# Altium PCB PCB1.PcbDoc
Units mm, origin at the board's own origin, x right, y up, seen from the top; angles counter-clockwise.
Board outline 114.17 x 52.7 mm, 2 copper layers (Top Layer, Bottom Layer); 27 components, 26 nets, 108 pads, 2 vias.
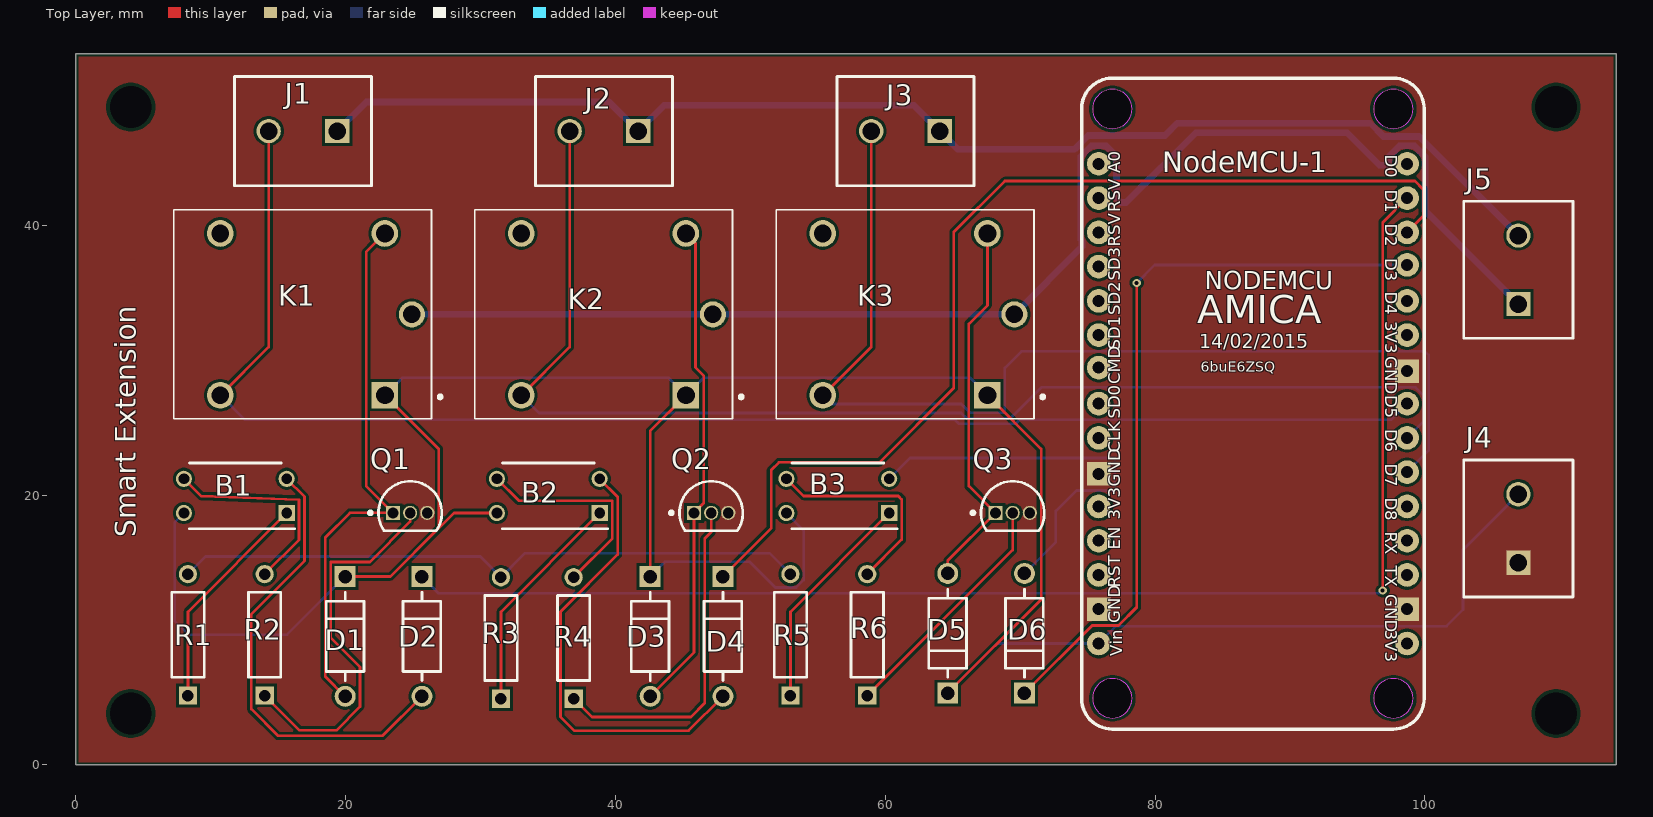
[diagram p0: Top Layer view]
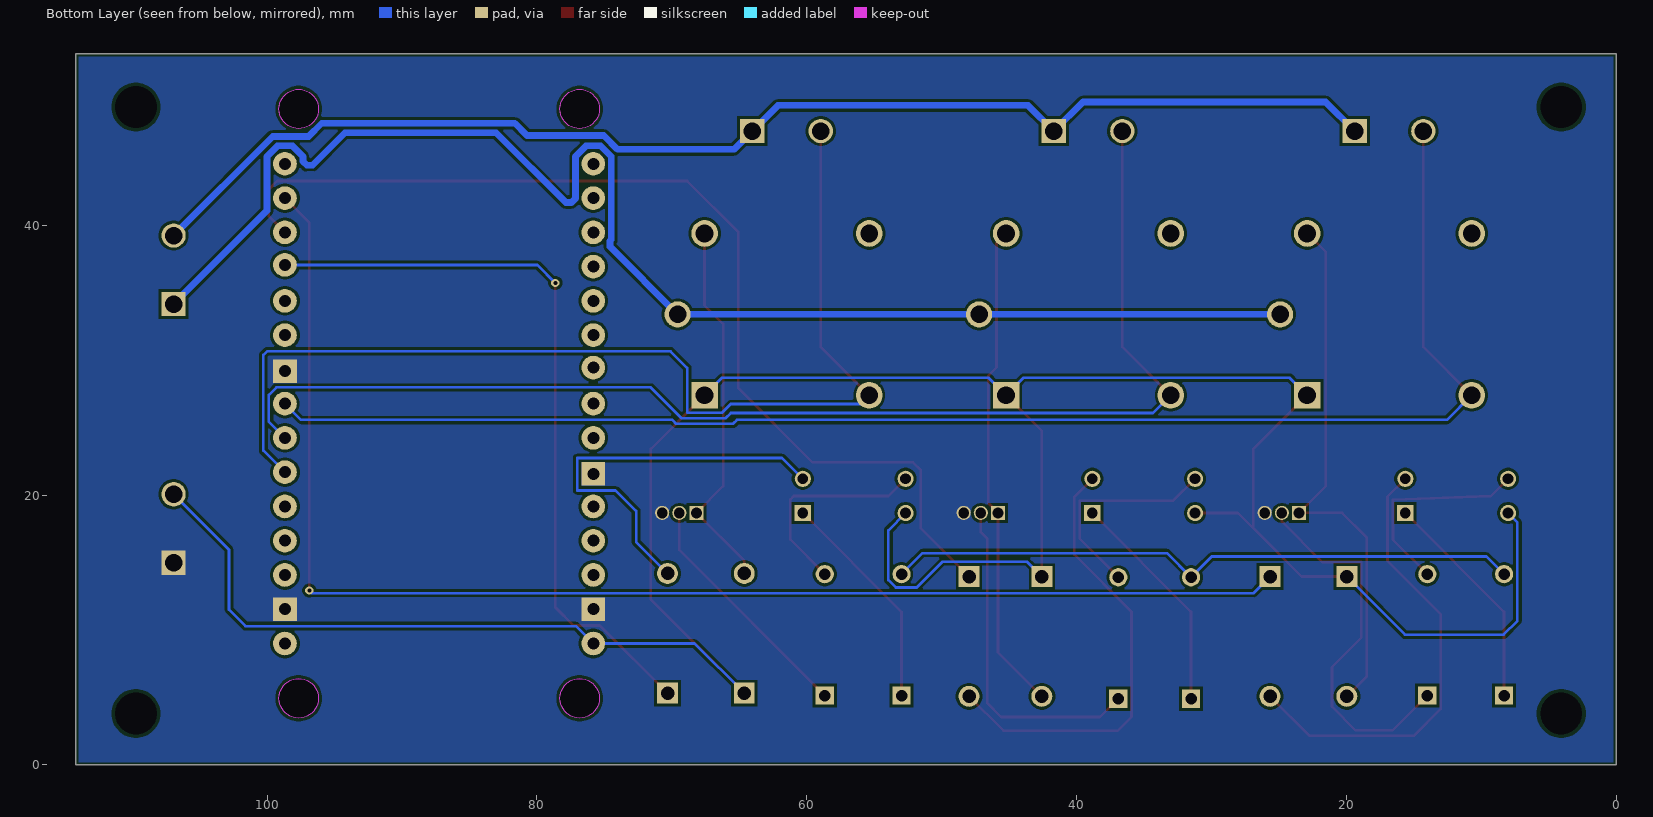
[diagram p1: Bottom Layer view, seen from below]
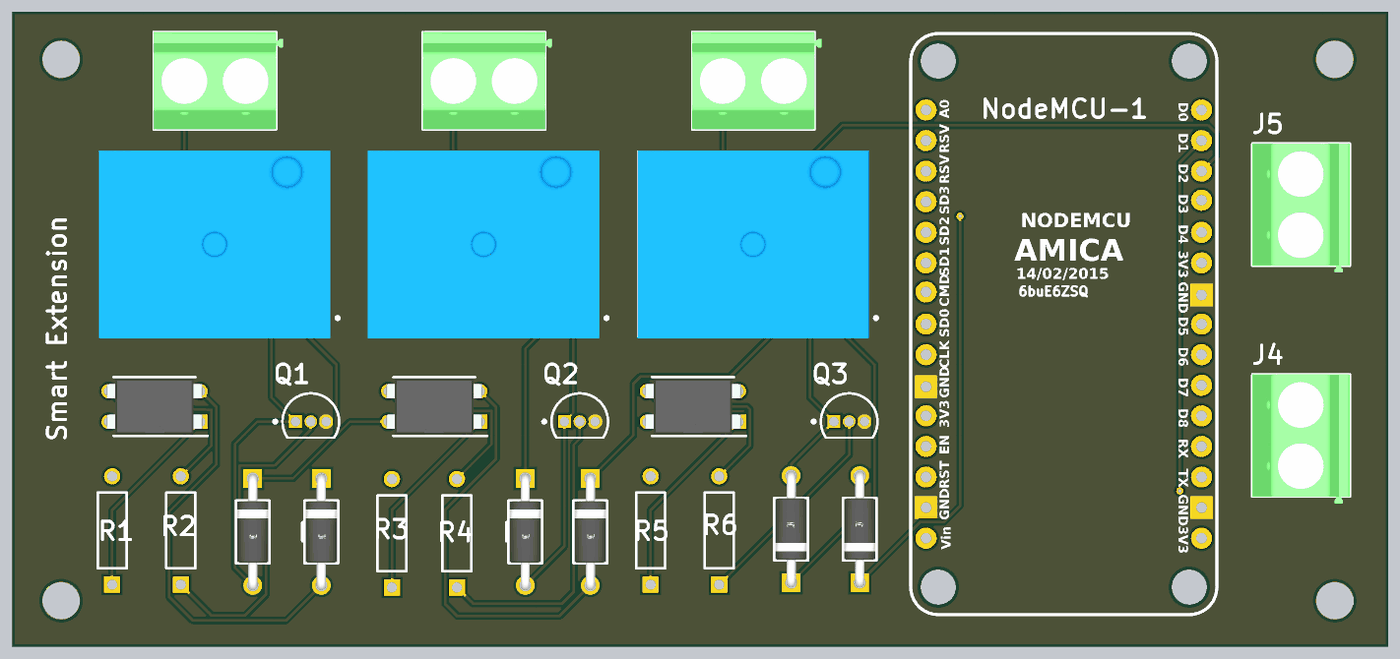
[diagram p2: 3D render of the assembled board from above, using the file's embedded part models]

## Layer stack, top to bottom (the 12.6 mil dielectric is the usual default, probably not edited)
Top Solder: solder mask 0.0102, Solder Resist, Dk 3.5
Top Layer: signal copper 0.0356
Dielectric 1: dielectric 0.32, FR-4, Dk 4.8
Bottom Layer: signal copper 0.0356
Bottom Solder: solder mask 0.0102, Solder Resist, Dk 3.5

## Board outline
0,0 114.173,0 114.173,52.705 0,52.705

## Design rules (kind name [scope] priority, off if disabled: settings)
BoardOutlineClearance [All] p1: gap=0.2 ignorepadtopadclearanceinfootprint=FALSE
Clearance [All] p1: gap=0.203 ignorepadtopadclearanceinfootprint=FALSE except(0.25: Arc-Hole Track-Hole SMDPad-Hole THPad-Hole Via-Hole Fill-Hole Poly-Hole Region-Hole Text-Hole)
ComponentClearance [All] p1: gap=0.127 collisioncheckmode=3 verticalgap=0.127 showdistances=TRUE
DiffPairsRouting [All] p1: maxlimit=0.381 minlimit=0.203 mostfreqgap=0.203 toplayer_minwidth=0.203 toplayer_maxwidth=25.4 toplayer_prefwidth=0.203 bottomlayer_minwidth=0.203 bottomlayer_maxwidth=25.4 bottomlayer_prefwidth=0.203 maxuncoupledlength=12.7
Height [All] p1: minheight=0 maxheight=1816.048 prefheight=12.7
HoleSize [All] p1: absolutevalues=TRUE maxlimit=6.3 minlimit=0.3 maxpercent=80.000 minpercent=20.000
HoleToHoleClearance [All] p1: gap=0.25 allowstackedmicrovias=FALSE
MinimumAnnularRing [All] p1: minimumring=0.076
MinimumSolderMaskSliver [All] p1: minsoldermaskwidth=0
PlaneClearance [All] p1: clearance=0.203
PlaneConnect PlaneConnectPowerPads [InPadClass('PowerPads')] p1: planeconnectstyle=Direct reliefexpansion=0.508 reliefentries=4 reliefconductorwidth=0.254 reliefairgap=0.254
PlaneConnect [All] p2: pad.planeconnectstyle=Relief pad.reliefexpansion=0.3 pad.reliefentries=4 pad.reliefconductorwidth=0.203 pad.reliefairgap=0.203 via.planeconnectstyle=Direct via.reliefexpansion=0.3 via.reliefentries=4 via.reliefconductorwidth=0.127 via.reliefairgap=0.127
PolygonConnect PolygonConnectPowerPads [All vs (InPadClass('PowerPads'))] p1: connectstyle=Direct reliefconductorwidth=0.254 reliefentries=4 polygonreliefangle="90 Angle" airgapwidth=0.254
PolygonConnect [All] p2: connectstyle=Direct reliefconductorwidth=0.203 reliefentries=4 polygonreliefangle="90 Angle" airgapwidth=0.203
RoutingVias [All] p1: holewidth=0.3 width=0.6 viastyle="Through Hole" minholewidth=0.3 minwidth=0.6 maxholewidth=0.6 maxwidth=6.6
SilkToSilkClearance [All] p1: silktosilkclearance=0
SilkToSolderMaskClearance [IsPad] p1: minsilkscreentomaskgap=0.127 clearancetoexposedcopper=TRUE
SolderMaskExpansion [All] p1: expansion=0.075 istentingtop=FALSE
Width [All] p1: maxlimit=25.4 minlimit=0.203 preferedwidth=0.203 minimp=50.000000 maximp=50.000000 favimp=50.000000
20 further rules are at their usual default settings.

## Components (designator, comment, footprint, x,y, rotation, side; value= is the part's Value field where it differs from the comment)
B1 "PC817X2NSZ0F" DIP762W60P254L458H400Q4N 11.811,19.939 r180 top
B2 "PC817X2NSZ0F" DIP762W60P254L458H400Q4N 35.015,19.939 r180 top
B3 "PC817X2NSZ0F" DIP762W60P254L458H400Q4N 56.478,19.939 r180 top
D1 "1N4007" FP-1N4007-MFG 19.959,9.525 r270 top value=15pF
D2 "1N4007" FP-1N4007-MFG 25.651,9.525 r270 top value=15pF
D3 "1N4007" FP-1N4007-MFG 42.571,9.525 r270 top value=15pF
D4 "1N4007" FP-1N4007-MFG 47.966,9.525 r270 top value=15pF
D5 "1N4007" FP-1N4007-MFG 64.626,9.755 r90 top value=15pF
D6 "1N4007" FP-1N4007-MFG 70.318,9.755 r90 top value=15pF
J1 "1729128" PHOE-1729128-2_V 16.829,46.99 r180 top
J2 "1729128" PHOE-1729128-2_V 39.144,46.99 r180 top
J3 "1729128" PHOE-1729128-2_V 61.496,46.99 r180 top
J4 "1729128" PHOE-1729128-2_V 106.934,17.526 r90 top
J5 "1729128" PHOE-1729128-2_V 106.934,36.703 r90 top
K1 "SRD-05VDC-SL-C" RELAY_SRD-05VDC-SL-C 16.801,33.401 r180 top
K2 "SRD-05VDC-SL-C" RELAY_SRD-05VDC-SL-C 39.116,33.401 r180 top
K3 "SRD-05VDC-SL-C" RELAY_SRD-05VDC-SL-C 61.468,33.401 r180 top
NodeMCU-1 "NodeMCU V1.0 ESP-12E" "NodeMCU V1.0 ESP-12E" 74.524,50.809 r0 top
Q1 "BC547B" ONSC-TO-92-3-29-11 24.776,18.684 r0 top
Q2 "BC547B" ONSC-TO-92-3-29-11 47.091,18.684 r0 top
Q3 "BC547B" ONSC-TO-92-3-29-11 69.443,18.684 r0 top
R1 "1K" RESA60-630X240 8.301,9.64 r90 top
R2 "1K" RESA60-630X240 13.993,9.64 r90 top
R3 "1K" RESA60-630X240 31.505,9.41 r90 top
R4 "1K" RESA60-630X240 36.9,9.41 r90 top
R5 "1K" RESA60-630X240 52.968,9.64 r90 top
R6 "1K" RESA60-630X240 58.66,9.64 r90 top

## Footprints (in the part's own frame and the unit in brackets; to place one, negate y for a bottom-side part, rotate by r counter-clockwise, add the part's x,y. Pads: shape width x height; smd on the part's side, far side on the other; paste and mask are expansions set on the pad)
DIP762W60P254L458H400Q4N [mm]
  rect 1.2x1.2 hole 0.8: 1(-3.81,1.27)
  round 1.2 hole 0.8: 2(-3.81,-1.27) 3(3.81,-1.27) 4(3.81,1.27)
  silkscreen extent -4.41,-2.44 3.4,2.44, body extent -3.96,-2.29 3.96,2.29, height 4
FP-1N4007-MFG [mm]
  rect 1.55x1.55 hole 1 paste-1000 mask+0: 1(-4.44,0)
  round 1.55 hole 1 paste-1000 mask+0: 2(4.44,0)
  silkscreen extent -3.27,-1.4 3.27,1.4, body extent -5.32,-1.5 5.32,1.5, height 0.25
"NodeMCU V1.0 ESP-12E" [mil]
  round 115 hole 115 unplated paste-300 mask-300: 0(91,-1806) 0(91,-86) 0(911,-1806) 0(911,-86)
  round 69 hole 35: 3V3(51,-1246) 3V3(951,-1646) 3V3(951,-746) A0(51,-246) CLK(51,-1046) CMD(51,-841) D0(951,-246) D1(951,-346) D2(951,-446) D3(951,-541) D4(951,-646) D5(951,-946) D6(951,-1046) D7(951,-1146) D8(951,-1246) EN(51,-1346) RST(51,-1446) RSV(51,-446) RSV(51,-346) RX(951,-1346) SD0(51,-946) SD1(51,-746) SD2(51,-646) SD3(51,-546) TX(951,-1446) VIN(51,-1646)
  rect 69x69 hole 35: GND(51,-1546) GND(51,-1151) GND(951,-1546) GND(951,-851)
  Keep-Out Layer circle w2: c911,-1806 r57.5
  Keep-Out Layer circle w2: c91,-1806 r57.5
  Keep-Out Layer circle w2: c911,-86 r57.5
  Keep-Out Layer circle w2: c91,-86 r57.5
  silkscreen extent 1,-1896 1001,4
ONSC-TO-92-3-29-11 [mm] "TO, 3-Leads, Body Dia 4.7mm, Pitch 1.27mm"
  rect 1.05x1.05 hole 0.8: 1(-1.27,0)
  round 1.05 hole 0.8: 2(0,0) 3(1.27,0)
  silkscreen extent -3.07,-1.34 2.35,2.35, body extent -2.35,-1.33 2.36,2.36, height 7.87
PHOE-1729128-2_V [mm] "Receptacle, 2-Leads, Body 8.1x10.16mm, Pitch 5.08mm"
  rect 1.8x1.8 hole 1.3: 1(-2.54,0)
  round 1.8 hole 1.3: 2(2.54,0)
  silkscreen extent -5.08,-4.05 5.08,4.05, body extent -5.65,-4.05 5.08,4.05, height 10.01
RELAY_SRD-05VDC-SL-C [mm]
  rect 1.98x1.98 / inner round 1.98 / far side rect 1.98x1.98 hole 1.32: A1(-6.1,6)
  round 1.98 hole 1.32: A2(-6.1,-6) NC(6.1,6) NO(6.1,-6)
  round 1.935 hole 1.29: COM(-8.1,0)
  silkscreen extent -10.3,-7.75 9.55,7.75, body extent -9.6,-7.8 9.6,7.8, height 15.8
RESA60-630X240 [mm] "Axial Resistor, 2-Leads, Dia 2.4mm, Body Length 6.3mm"
  rect 1.35x1.35 hole 0.85: 1(-4.5,0)
  round 1.35 hole 0.85: 2(4.5,0)
  silkscreen extent -3.15,-1.2 3.15,1.2, body extent -3.15,-1.2 3.15,1.2, height 2.4

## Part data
B1 B2 B3: "Photocoupler 1-CH Transistor 4-Pin PDIP Sharp PC817X2NSZ0F DC Input Transistor Output Optocoupler, Through Hole, 4-Pin PDIP", Manufacturer_Name="Sharp Microelectronics", Mouser Part Number=N/A
D1 D2 D3 D4 D5 D6: library part CMP-123542-000001-1, "Rectifier diode 1000 V 1 A DO-41, ,", Capacitance=15pF, Forward Current=1A, Manufacturer=Diotec, Max Junction Temp=+175°C, Max Repetitive Reverse Voltage=1000V, Max Surge Forward Current=27A, Peak Reverse Current=5uA, Temperature="-50°C to +175°C", Temperature Range Low=-50°C
J1 J2 J3 J4 J5: library part CMP-2000-05815-1, "PCB Terminal Block, 13.5 A, 400 V, 2-Pin THD, RoHS, Bulk", Current Rating=13500mA, Manufacturer="Phoenix Contact", Package Description="2-Pin Through Hole Device, Body 8.1 x 10.16 mm, Pitch 5.08 mm", Package Reference=1729128-2, Package Version=03/2015, Voltage Rating=400V
K1 K2 K3: "5V Trigger Relay Module For Arduino And Raspberry Pi 5V Trigger Relay Module For Arduino And Raspberry Pi", Package="NON STANDARD-5 Songle Relay"
NodeMCU-1: "NodeMCU V1.0 ESP8266 (ESP-12E)"
Q1 Q2 Q3: library part CMP-1048-01467-1, "Amplifier Transistor, NPN Silicon, 3-Pin TO-92, Bulk Box", Manufacturer="On Semiconductor"
R1 R2 R3 R4 R5 R6: library part CMP-1659-00075-1, "Axial Resistor, 1 KOhm, +/- 1%, 250 mW, -55 to 155 degC, 2-Pin THD, RoHS, Bulk", Case\Package=Axial, Max Operating Temperature="155 degC", Min Operating Temperature="-55 degC", Package Quantity=200, Power Rating="250 mW", Resistance="10 kohm", Tolerance=1%, Voltage Rating="250 V"

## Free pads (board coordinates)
  round 1.524 hole 3.1: 1(4.064,48.768) 1(109.728,3.81) 1(109.728,48.768) 4(4.064,3.81)

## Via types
v1: diameter 0.6, hole 0.3, Top Layer to Bottom Layer, 2 vias

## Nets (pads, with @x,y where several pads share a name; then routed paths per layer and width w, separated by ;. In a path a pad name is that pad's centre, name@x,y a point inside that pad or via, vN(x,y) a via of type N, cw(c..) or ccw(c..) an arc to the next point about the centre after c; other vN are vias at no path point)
+5: B1.4 B2.4 B3.4 D1.1 D3.1 D5.1 J4.2 K1.A1 K2.A1 K3.A1 NodeMCU-1.VIN | length 210.2
  Top Layer w0.203: D1.1 23.312,13.965 ; K1.A1 26.899,23.403 26.899,17.551 23.312,13.965 ; B2.4 28.021,18.669 23.317,13.965 23.312,13.965 ; D3.1 42.571,24.756 K2.A1 ; D5.1 71.552,12.24 71.552,23.417 K3.A1
  Bottom Layer w0.203: B1.4 7.315,17.983 7.315,10.668 8.331,9.652 15.646,9.652 D1.1 ; K1.A1 24.202,28.702 43.915,28.702 K2.A1 46.517,28.702 66.267,28.702 K3.A1 ; D3.1 43.668,15.062 49.936,15.062 51.841,13.157 53.391,13.157 53.95,13.716 53.95,17.387 B3.4 ; D5.1 68.312,9.001 NodeMCU-1.VIN 77.105,10.287 101.6,10.287 102.819,11.506 102.819,15.951 J4.2
+5V: R1.2 R3.2 R5.2 | length 47.2
  Bottom Layer w0.203: R1.2 9.604,15.443 29.972,15.443 R3.2 33.292,15.697 51.411,15.697 R5.2
GND: J4.1 NodeMCU-1.GND Q1.3 Q2.3 Q3.3
N: J1.1 J2.1 J3.1 J5.2 | length 95.7
  Bottom Layer w0.5: J1.1 21.528,49.149 39.525,49.149 J2.1 43.589,48.895 62.131,48.895 65.393,45.633 74.016,45.633 75.048,46.664 80.736,46.664 81.638,47.566 95.949,47.566 96.922,46.594 99.583,46.594 J5.2
NetB1_1: B1.1 R1.1 | length 16.6
  Top Layer w0.203: R1.1 8.301,11.349 B1.1
NetB1_2: B1.2 D2.2 | length 33.9
  Top Layer w0.203: B1.2 16.942,19.888 16.942,15.113 13.005,11.176 13.005,4.14 14.986,2.159 22.725,2.159 D2.2
NetB1_3: B1.3 R2.2 | length 15.6
  Top Layer w0.203: B1.3 9.271,19.939 16.535,19.66 16.535,16.683 R2.2
NetB2_1: B2.1 R3.1 | length 16.8
  Top Layer w0.203: R3.1 31.505,11.349 B2.1
NetB2_2: B2.2 D4.2 | length 33.5
  Top Layer w0.203: B2.2 40.157,19.877 40.157,15.596 35.916,11.354 35.916,3.556 36.932,2.54 45.421,2.54 D4.2
NetB2_3: B2.3 R4.2 | length 16.1
  Top Layer w0.203: B2.3 32.831,19.583 39.751,19.583 39.751,16.761 R4.2
NetB3_1: B3.1 R5.1 | length 16.6
  Top Layer w0.203: R5.1 52.968,11.349 B3.1
NetB3_2: B3.2 D6.2 | length 30.4
  Bottom Layer w0.203: B3.2 61.837,22.758 77.013,22.758 77.013,20.345 74.168,20.345 72.644,18.821 72.644,16.521 D6.2
NetB3_3: B3.3 R6.2 | length 15.8
  Top Layer w0.203: B3.3 53.938,19.939 60.96,19.939 61.214,19.685 61.214,16.694 R6.2
NetD1_2: D1.2 K1.A2 Q1.1 | length 40.3
  Top Layer w0.203: D1.2 18.473,6.571 18.473,16.837 20.32,18.684 Q1.1 21.514,20.676 21.514,38.014 K1.A2
NetD3_2: D3.2 K2.A2 Q2.1 | length 36.5
  Top Layer w0.203: D3.2 45.821,8.335 Q2.1 46.533,19.396 46.533,28.854 45.923,29.464 45.923,38.694 K2.A2
NetD5_2: D5.2 K3.A2 Q3.1 | length 28.1
  Top Layer w0.203: D5.2 64.626,15.137 Q3.1 66.192,20.665 66.192,32.69 67.568,34.065 K3.A2
NetQ1_2: Q1.2 R2.1 | length 28.3
  Top Layer w0.203: R2.1 16.567,2.565 19.304,2.565 21.057,4.318 21.057,7.264 18.88,9.441 18.88,15.045 21.787,15.045 24.776,18.034 Q1.2
NetQ2_2: Q2.2 R4.1 | length 25
  Top Layer w0.203: R4.1 38.254,3.556 45.593,3.556 46.609,4.572 46.609,16.764 47.091,17.246 Q2.2
NetQ3_2: Q3.2 R6.1 | length 18
  Top Layer w0.203: R6.1 69.443,15.923 Q3.2
Out1_1: J1.2 K1.NC NodeMCU-1.D5 | length 110.5
  Top Layer w0.203: K1.NC 14.289,30.989 J1.2
  Bottom Layer w0.203: K1.NC 12.524,25.578 65.176,25.578 65.46,25.293 69.676,25.293 69.96,25.578 97.476,25.578 NodeMCU-1.D5
Out2_1: J2.2 K2.NC NodeMCU-1.D6 | length 93.5
  Top Layer w0.203: K2.NC 36.604,30.989 J2.2
  Bottom Layer w0.203: K2.NC 34.331,26.086 65.621,26.086 66.007,25.7 69.269,25.7 71.56,27.991 99.314,27.991 99.873,27.432 99.873,25.435 NodeMCU-1.D6
Out3_1: J3.2 K3.NC NodeMCU-1.D7 | length 79.8
  Top Layer w0.203: K3.NC 58.956,30.989 J3.2
  Bottom Layer w0.203: K3.NC 56.023,26.746 65.629,26.746 66.269,26.106 68.863,26.106 68.863,29.417 70.104,30.658 100,30.658 100.279,30.378 100.279,23.301 NodeMCU-1.D7
P: J5.1 K1.COM K2.COM K3.COM | length 106
  Bottom Layer w0.5: K1.COM K2.COM K3.COM 74.586,38.419 74.586,38.834 74.49,38.93 74.49,45.112 75.268,45.89 76.37,45.89 77.148,45.112 77.148,41.981 77.441,41.689 77.856,41.689 83.03,46.863 94.234,46.863 96.642,44.455 97.057,44.455 97.35,44.747 97.35,45.112 98.128,45.89 99.23,45.89 100.008,45.112 100.008,41.089 J5.1
Relay1_1: D2.1 NodeMCU-1.D1 | length 101.7
  Top Layer w0.203: v1(96.876,12.929) 96.876,40.218 NodeMCU-1.D1
  Bottom Layer w0.203: D2.1 26.891,12.725 96.672,12.725 v1(96.876,12.929)
Relay2_1: D4.1 NodeMCU-1.D2 | length 77.3
  Top Layer w0.203: D4.1 51.537,17.536 51.537,21.844 52.121,22.428 59.563,22.428 65.075,27.94 65.075,39.497 68.859,43.282 99.263,43.282 99.873,42.672 99.873,40.675 NodeMCU-1.D2
Relay3_1: D6.1 NodeMCU-1.D3 | length 55.6
  Top Layer w0.203: D6.1 75.341,10.338 77.292,10.338 78.638,11.684 v1(78.638,35.738)
  Bottom Layer w0.203: v1(78.638,35.738) 79.969,37.068 NodeMCU-1.D3
pads on no net: K1.NO K2.NO K3.NO NodeMCU-1.0 NodeMCU-1.3V3 NodeMCU-1.A0 NodeMCU-1.CLK NodeMCU-1.CMD NodeMCU-1.D0 NodeMCU-1.D4 NodeMCU-1.D8 NodeMCU-1.EN NodeMCU-1.RST NodeMCU-1.RSV NodeMCU-1.RX NodeMCU-1.SD0 NodeMCU-1.SD1 NodeMCU-1.SD2 NodeMCU-1.SD3 NodeMCU-1.TX

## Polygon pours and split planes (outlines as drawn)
GND on Bottom Layer "GND_L02_P000" (solid, pour order 0): 0,0 114.173,0 114.173,52.705 0,52.705
GND on Top Layer "GND_L01_P001" (solid, pour order 1): 0,0 114.173,0 114.173,52.705 0,52.705

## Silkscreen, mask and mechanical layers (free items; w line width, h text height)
Top Overlay:
  text "Smart Extension" at 4.445,16.891 h1.52 r90
Mechanical 1:
  lines w0.254: 0,0.254 0,52.832 114.173,52.832 114.173,0.254 114.3,0.127 0.127,0.127 0,0.254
